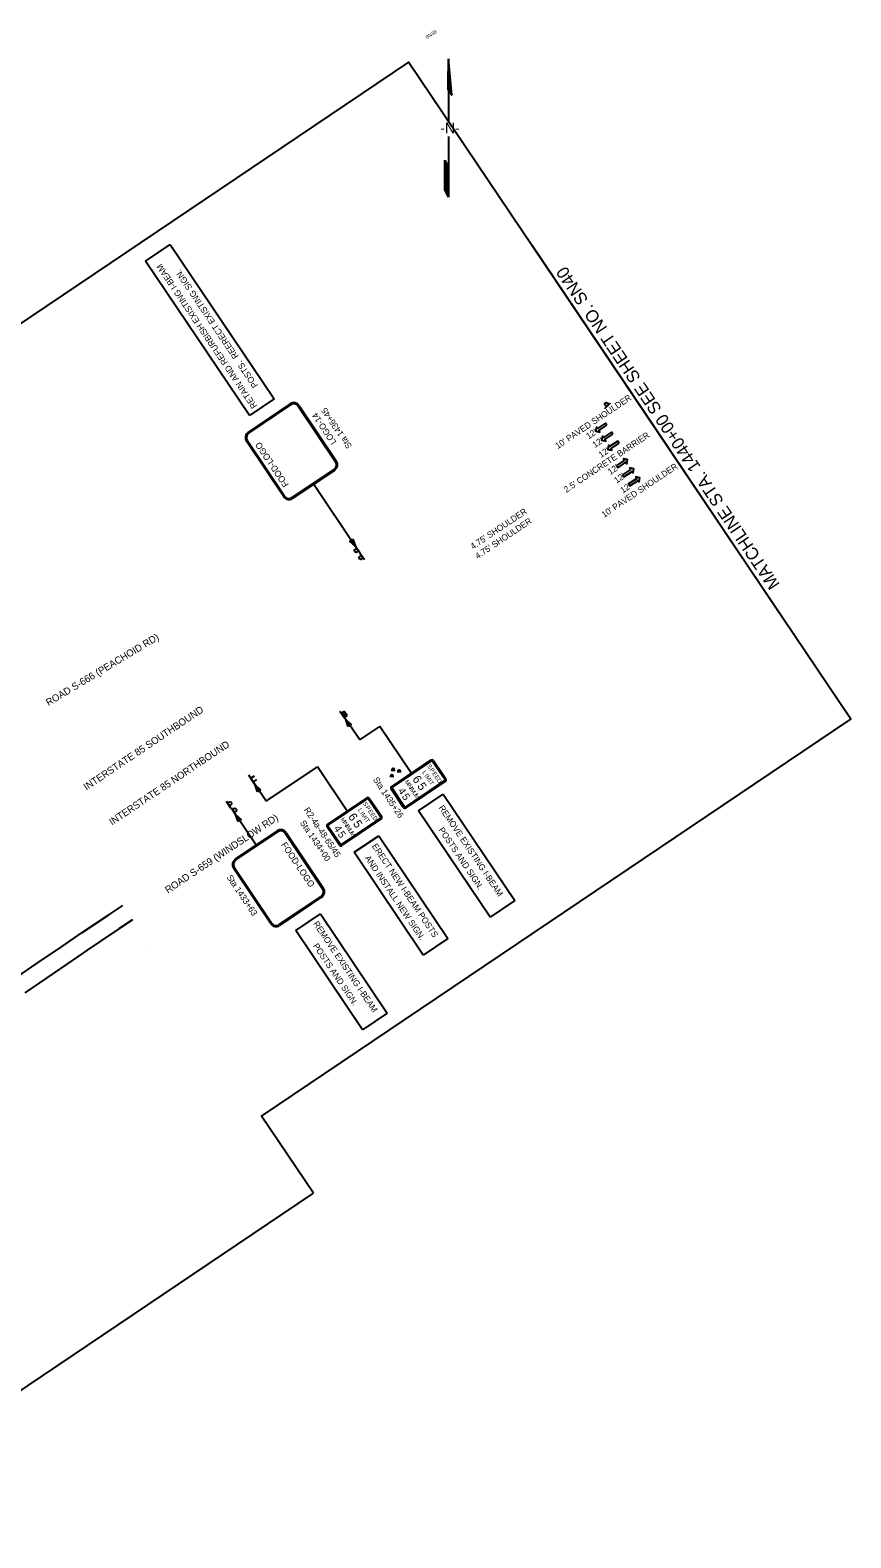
# Model space of a CAD drawing. Extents: x 1790709 to 1792453, y 1184078 to 1185781.
# Drawn here: x 1791525 to 1792453, y 1184078 to 1185781 of the extents above; entities that cross this region are included whole.
import ezdxf

# ---------------------------------------------------------------- set-up
doc = ezdxf.new("R2010")
doc.units = 0
for name, color, linetype in [('RD_EX_Road', 7, 'Continuous'), ('RD_PD_Final_LnLine', 7, 'Continuous'), ('RD_PD_Final_TX', 7, 'Continuous'), ('RD_SHT_MatchLine', 7, 'Continuous'), ('RD_SHT_ShtClip', 7, 'Continuous'), ('RD_SHT_TX', 7, 'Continuous'), ('RD_Sketch1', 7, 'Continuous'), ('RD_TX_RoadID', 7, 'Continuous'), ('SN_P_Signs', 7, 'Continuous')]:
    doc.layers.add(name, color=color, linetype=linetype)

# ---------------------------------------------------------------- blocks, each defined once
blk = doc.blocks.new('NA5')
at = {"layer": 'RD_Sketch1'}
for p, q in [((47.5, 65.9), (26.8, 37.4)), ((26.8, 30.6), (47.5, 65.9)), ((27.2, 37.5), (14.5, 19.8)), ((28.1, 38.3), (26.8, 30.6)), ((14.5, 19.8), (5.5, 7.2)), ((-3.5, -5.3), (-18.5, -26.3)), ((-18.5, -26.3), (-43.3, -60.9)), ((-30.6, -36.2), (-22.3, -24.7)), ((-22.3, -24.7), (-24, -34)), ((-41.6, -51.6), (-30.6, -36.2)), ((-43.3, -60.9), (-41.6, -51.6))]:
    blk.add_line(p, q, dxfattribs=at)
for points in [[(27.1, 37.6), (39.2, 54.5)], [(27.4, 37.8), (47.4, 65.8)], [(27.6, 37.9), (46.9, 64.9)], [(27.6, 35.5), (39, 51.5)], [(27.7, 36.2), (40.6, 54.2)], [(27.7, 36), (40.1, 53.3)], [(27.7, 35.8), (39.6, 52.4)], [(27.8, 38.1), (46.4, 64)], [(27.8, 36.8), (42.2, 56.8)], [(27.8, 36.6), (41.7, 56)], [(27.8, 36.4), (41.1, 55.1)], [(27.9, 37.4), (43.8, 59.5)], [(27.9, 37.2), (43.2, 58.6)], [(27.9, 37), (42.7, 57.7)], [(28, 38.1), (45.3, 62.2)], [(28, 37.9), (44.8, 61.3)], [(28, 37.7), (44.3, 60.4)], [(28.1, 38.3), (45.8, 63.1)], [(26.9, 37.5), (29.9, 41.7)], [(27, 32), (30.1, 36.3)], [(27, 31.8), (29.6, 35.4)], [(27, 31.5), (29.1, 34.5)], [(27.1, 32.6), (31.7, 39)], [(27.1, 32.4), (31.2, 38.1)], [(27.1, 32.2), (30.6, 37.2)], [(27.2, 33.2), (33.3, 41.6)], [(27.2, 33), (32.7, 40.7)], [(27.2, 32.8), (32.2, 39.9)], [(27.3, 33.9), (34.8, 44.3)], [(27.3, 33.7), (34.3, 43.4)], [(27.3, 33.4), (33.8, 42.5)], [(27.4, 34.5), (36.4, 47)], [(27.4, 34.3), (35.9, 46.1)], [(27.4, 34.1), (35.4, 45.2)], [(27.5, 34.9), (37.5, 48.8)], [(27.5, 34.7), (36.9, 47.9)], [(27.6, 35.3), (38.5, 50.6)], [(27.6, 35.1), (38, 49.7)], [(26.8, 30.7), (27, 30.9)], [(26.9, 31.3), (28.5, 33.6)], [(26.9, 31.1), (28, 32.7)], [(26.9, 30.9), (27.5, 31.8)], [(-43.3, -60.8), (-24, -33.9)], [(-43.2, -60.1), (-23.9, -33.2)], [(-43.2, -60.3), (-23.9, -33.4)], [(-43.2, -60.5), (-24, -33.6)], [(-43.1, -59.7), (-23.8, -32.8)], [(-43.1, -59.9), (-23.9, -33)], [(-43, -59), (-23.7, -32.1)], [(-43, -59.2), (-23.7, -32.3)], [(-43, -59.4), (-23.8, -32.5)], [(-42.9, -58.6), (-23.6, -31.7)], [(-42.9, -58.8), (-23.7, -31.9)], [(-42.8, -58.1), (-23.5, -31.2)], [(-42.8, -58.3), (-23.6, -31.4)], [(-42.7, -57.5), (-23.4, -30.6)], [(-42.7, -57.7), (-23.5, -30.8)], [(-42.7, -57.9), (-23.5, -31)], [(-42.6, -57), (-23.3, -30.1)], [(-42.6, -57.2), (-23.4, -30.4)], [(-42.5, -56.4), (-23.2, -29.5)], [(-42.5, -56.6), (-23.2, -29.7)], [(-42.5, -56.8), (-23.3, -29.9)], [(-42.4, -55.9), (-23.1, -29)], [(-42.4, -56.1), (-23.2, -29.3)], [(-42.3, -55.3), (-23, -28.4)], [(-42.3, -55.5), (-23, -28.6)], [(-42.3, -55.7), (-23.1, -28.8)], [(-42.2, -54.8), (-22.9, -27.9)], [(-42.2, -55), (-23, -28.2)], [(-42.1, -54.4), (-22.8, -27.5)], [(-42.1, -54.6), (-22.9, -27.7)], [(-42, -53.7), (-22.7, -26.8)], [(-42, -53.9), (-22.7, -27.1)], [(-42, -54.2), (-22.8, -27.3)], [(-41.9, -53.3), (-22.6, -26.4)], [(-41.9, -53.5), (-22.7, -26.6)], [(-41.8, -52.6), (-22.5, -25.7)], [(-41.8, -52.8), (-22.5, -26)], [(-41.8, -53.1), (-22.6, -26.2)], [(-41.7, -52.2), (-22.4, -25.3)], [(-41.7, -52.4), (-22.5, -25.5)], [(-41.6, -51.7), (-22.3, -24.9)], [(-41.6, -52), (-22.4, -25.1)]]:
    blk.add_lwpolyline(points, dxfattribs=at)
blk.add_text('-N-', height=11.81, rotation=324.3865, dxfattribs=at).set_placement((-8.8, 3))
blk = doc.blocks.new('SARRW2')
at = {"layer": 'RD_PD_Final_LnLine'}
blk.add_lwpolyline([(-12, 1.2), (-12, -1.2), (-2.8, -1.2), (-2.8, -2.8), (0, 0), (-2.8, 2.8), (-2.8, 1.2)], close=True, dxfattribs=at)

msp = doc.modelspace()

# ---------------------------------------------------------------- linework, layer by layer
at = {"layer": 'RD_EX_Road'}
for points in [[(1791510, 1184711.3), (1791533.3, 1184727.1), (1791561.9, 1184746.4), (1791584.1, 1184761.6), (1791614, 1184781.7), (1791629.9, 1184792.4)], [(1791640.9, 1184776.1), (1791625.5, 1184765.8), (1791604.7, 1184751.9), (1791589.6, 1184741.6), (1791573.9, 1184731), (1791544, 1184710.6), (1791519.1, 1184693.7)]]:
    msp.add_lwpolyline(points, dxfattribs=at)
at = {"layer": 'RD_SHT_MatchLine'}
msp.add_lwpolyline([(1792371.8, 1185122.9), (1792232.2, 1185330.3), (1792092.6, 1185537.7)], dxfattribs=at)
at = {"layer": 'RD_SHT_ShtClip'}
msp.add_lwpolyline([(1791845.3, 1184467.1), (1791786.7, 1184554.2), (1792452.8, 1185002.6), (1791953, 1185745.1), (1791953, 1185745.1), (1790708.7, 1184907.4), (1791267.1, 1184077.9)], close=True, dxfattribs=at)
at = {"layer": 'SN_P_Signs'}
for p, q in [((1791655.7, 1185520.1), (1791683.6, 1185538.9)), ((1791683.6, 1185538.9), (1791800.9, 1185364.7)), ((1791773, 1185345.9), (1791655.7, 1185520.1)), ((1791800.9, 1185364.7), (1791773, 1185345.9)), ((1792174.9, 1185353.8), (1792181.3, 1185360.1)), ((1791845.7, 1185268.1), (1791892.9, 1185197.9)), ((1791897.9, 1185190.5), (1791892.9, 1185197.9)), ((1791903, 1185182.6), (1791898, 1185190.1)), ((1791875.4, 1185011.8), (1791880.4, 1185004.3)), ((1791876.9, 1185010), (1791882, 1185002.5)), ((1791897.7, 1184979.2), (1791882, 1185002.5)), ((1791897.7, 1184979.2), (1791920.4, 1184994.5)), ((1791956.1, 1184941.5), (1791920.4, 1184994.5)), ((1791791.9, 1184910), (1791849.9, 1184949)), ((1791883.6, 1184898.9), (1791849.9, 1184949)), ((1791933.4, 1184945.2), (1791937.9, 1184945.2)), ((1791933.7, 1184926.4), (1791978.5, 1184956.6)), ((1791981, 1184956.1), (1791995.1, 1184935.2)), ((1791779.4, 1184928.4), (1791772.2, 1184939.3)), ((1791774.5, 1184935.9), (1791778.6, 1184938.6)), ((1791777.3, 1184931.7), (1791781.4, 1184934.5)), ((1791791.9, 1184910), (1791779.4, 1184928.4)), ((1791931.8, 1184938.3), (1791936.3, 1184938.3)), ((1791940.1, 1184943.5), (1791944.6, 1184943.5)), ((1791994.6, 1184932.7), (1791949.8, 1184902.5)), ((1791861.2, 1184883.9), (1791906, 1184914)), ((1791908.5, 1184913.5), (1791922.6, 1184892.6)), ((1791947.3, 1184903), (1791933.2, 1184923.9)), ((1791964.2, 1184899.3), (1791992.1, 1184918.1)), ((1791992.1, 1184918.1), (1792073.1, 1184797.8)), ((1791746.7, 1184910), (1791751.7, 1184902.6)), ((1791752.3, 1184902.6), (1791757.4, 1184895.2)), ((1791780.7, 1184860.5), (1791757.4, 1184895.2)), ((1792045.2, 1184779), (1791964.2, 1184899.3)), ((1791874.8, 1184860.5), (1791860.7, 1184881.4)), ((1791922.1, 1184890.1), (1791877.3, 1184860)), ((1791891.4, 1184852.3), (1791919.2, 1184871.1)), ((1791919.2, 1184871.1), (1791997.4, 1184754.9)), ((1791969.5, 1184736.2), (1791891.4, 1184852.3)), ((1792073.1, 1184797.8), (1792045.2, 1184779)), ((1791825.5, 1184763.9), (1791853.4, 1184782.7)), ((1791853.4, 1184782.7), (1791928.8, 1184670.7)), ((1791900.9, 1184651.9), (1791825.5, 1184763.9)), ((1791660.4, 1184747.2), (1791660.4, 1184747.2)), ((1791997.4, 1184754.9), (1791969.5, 1184736.2)), ((1791928.8, 1184670.7), (1791900.9, 1184651.9))]:
    msp.add_line(p, q, dxfattribs=at)
for points in [[(1791771.5, 1185326.7), (1791819.3, 1185358.9)], [(1791772.2, 1185325.7), (1791820, 1185357.9)], [(1791828.3, 1185356.2), (1791870.5, 1185293.5)], [(1791829.3, 1185356.9), (1791871.5, 1185294.2)], [(1791811.8, 1185254), (1791769.6, 1185316.7)], [(1791812.8, 1185254.7), (1791770.6, 1185317.4)], [(1791868.9, 1185285.2), (1791821.1, 1185253)], [(1791869.5, 1185284.2), (1791821.8, 1185252)], [(1791934, 1184926), (1791978.8, 1184956.2)], [(1791934.4, 1184925.4), (1791979.2, 1184955.6)], [(1791980, 1184955.4), (1791994.1, 1184934.5)], [(1791980.7, 1184955.8), (1791994.7, 1184934.9)], [(1791993.9, 1184933.7), (1791949.1, 1184903.5)], [(1791994.4, 1184933), (1791949.6, 1184902.9)], [(1791861.4, 1184883.5), (1791906.2, 1184913.6)], [(1791861.9, 1184882.9), (1791906.7, 1184913)], [(1791907.5, 1184912.9), (1791921.6, 1184892)], [(1791908.1, 1184913.3), (1791922.2, 1184892.4)], [(1791947.7, 1184903.2), (1791933.6, 1184924.2)], [(1791948.3, 1184903.7), (1791934.2, 1184924.6)], [(1791756.8, 1184844.4), (1791804.6, 1184876.5)], [(1791875.2, 1184860.7), (1791861.1, 1184881.6)], [(1791875.8, 1184861.1), (1791861.7, 1184882)], [(1791921.4, 1184891.1), (1791876.6, 1184861)], [(1791921.8, 1184890.5), (1791877, 1184860.3)], [(1791757.5, 1184843.4), (1791805.3, 1184875.5)], [(1791813.6, 1184873.9), (1791855.8, 1184811.2)], [(1791814.6, 1184874.6), (1791856.8, 1184811.9)], [(1791797.1, 1184771.7), (1791754.9, 1184834.4)], [(1791798.1, 1184772.3), (1791755.9, 1184835)], [(1791854.2, 1184802.9), (1791806.4, 1184770.7)], [(1791854.9, 1184801.9), (1791807.1, 1184769.7)]]:
    msp.add_lwpolyline(points, dxfattribs=at)
for points in [[(1791890, 1185205.9), (1791892.9, 1185197.9), (1791886.6, 1185203.6)], [(1791884.8, 1184994.5), (1791882, 1185002.5), (1791888.2, 1184996.8)], [(1791782.3, 1184920.5), (1791779.4, 1184928.4), (1791785.7, 1184922.8)], [(1791760.2, 1184887.2), (1791757.4, 1184895.2), (1791763.6, 1184889.5)]]:
    msp.add_lwpolyline(points, close=True, dxfattribs=at)
for centre, radius in [((1792176.7, 1185358.4), 2), ((1791893.7, 1185193.1), 2), ((1791898.8, 1185185.2), 2), ((1791879.6, 1185009.2), 2), ((1791881.1, 1185007.3), 2), ((1791935.6, 1184946.2), 1), ((1791942.3, 1184944.5), 1), ((1791934.1, 1184939.3), 1), ((1791750.9, 1184907.4), 2), ((1791756.5, 1184900), 2)]:
    msp.add_circle(centre, radius, dxfattribs=at)
for centre, radius, start, end in [((1791823.3, 1185352.9), 7.2, 33.9476, 123.9476), ((1791823.3, 1185352.9), 6, 33.9476, 123.9476), ((1791775.5, 1185320.7), 7.2, 123.9476, 213.9476), ((1791775.5, 1185320.7), 6, 123.9476, 213.9476), ((1791865.5, 1185290.2), 6, 303.9476, 33.9476), ((1791865.5, 1185290.2), 7.2, 303.9476, 33.9476), ((1791817.7, 1185258), 7.2, 213.9476, 303.9476), ((1791817.7, 1185258), 6, 213.9476, 303.9476), ((1791979.5, 1184955.1), 1.8, 33.9476, 123.9476), ((1791979.5, 1184955.1), 1.35, 33.9476, 123.9476), ((1791979.5, 1184955.1), 0.6, 33.9476, 123.9476), ((1791993.6, 1184934.2), 0.6, 303.9476, 33.9476), ((1791993.6, 1184934.2), 1.35, 303.9476, 33.9476), ((1791993.6, 1184934.2), 1.8, 303.9476, 33.9476), ((1791907, 1184912.5), 1.8, 33.9476, 123.9476), ((1791907, 1184912.5), 1.35, 33.9476, 123.9476), ((1791907, 1184912.5), 0.6, 33.9476, 123.9476), ((1791934.7, 1184924.9), 1.8, 123.9476, 213.9476), ((1791934.7, 1184924.9), 1.35, 123.9476, 213.9476), ((1791934.7, 1184924.9), 0.6, 123.9476, 213.9476), ((1791948.8, 1184904), 1.8, 213.9476, 303.9476), ((1791948.8, 1184904), 1.35, 213.9476, 303.9476), ((1791948.8, 1184904), 0.6, 213.9476, 303.9476), ((1791808.6, 1184870.6), 7.2, 33.9476, 123.9476), ((1791808.6, 1184870.6), 6, 33.9476, 123.9476), ((1791862.2, 1184882.4), 1.8, 123.9476, 213.9476), ((1791862.2, 1184882.4), 1.35, 123.9476, 213.9476), ((1791862.2, 1184882.4), 0.6, 123.9476, 213.9476), ((1791921.1, 1184891.6), 0.6, 303.9476, 33.9476), ((1791921.1, 1184891.6), 1.35, 303.9476, 33.9476), ((1791921.1, 1184891.6), 1.8, 303.9476, 33.9476), ((1791876.3, 1184861.5), 1.8, 213.9476, 303.9476), ((1791876.3, 1184861.5), 1.35, 213.9476, 303.9476), ((1791876.3, 1184861.5), 0.6, 213.9476, 303.9476), ((1791760.9, 1184838.4), 7.2, 123.9476, 213.9476), ((1791760.9, 1184838.4), 6, 123.9476, 213.9476), ((1791850.9, 1184807.8), 6, 303.9476, 33.9476), ((1791850.9, 1184807.8), 7.2, 303.9476, 33.9476), ((1791803.1, 1184775.7), 7.2, 213.9476, 303.9476), ((1791803.1, 1184775.7), 6, 213.9476, 303.9476)]:
    msp.add_arc(centre, radius, start, end, dxfattribs=at)

# ---------------------------------------------------------------- block references
at = {"layer": 'RD_PD_Final_LnLine', "xscale": 1.1999999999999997}
for p, yscale, rotation in [((1792164.3, 1185328), 1.2000000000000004, -146.05256015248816), ((1792171.1, 1185317.8), 1.2000000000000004, -146.05256015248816), ((1792178.1, 1185307.5), 1.2000000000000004, -146.05256015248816), ((1792200.5, 1185296), 1.2, 33.94743984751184), ((1792207.5, 1185285.6), 1.2, 33.94743984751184), ((1792214.3, 1185275.4), 1.2, 33.94743984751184)]:
    msp.add_blockref('SARRW2', p, dxfattribs=dict(at, yscale=yscale, rotation=rotation))
at = {"layer": 'RD_SHT_MatchLine', "rotation": 35.61349782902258}
msp.add_blockref('NA5', (1791997.7, 1185667.3), dxfattribs=at)

# ---------------------------------------------------------------- texts
at = {"layer": 'RD_PD_Final_TX'}
for s, p in [("10' PAVED SHOULDER", (1792121.6, 1185307.7)), ("2.5' CONCRETE BARRIER", (1792131.3, 1185258.2)), ("12'", (1792156.4, 1185318.7)), ("12'", (1792163.6, 1185309)), ("12'", (1792170.5, 1185297.7)), ("10' PAVED SHOULDER", (1792173.9, 1185230.1)), ("12'", (1792181, 1185278.4)), ("12'", (1792188.1, 1185268.8)), ("12'", (1792195.1, 1185257.5)), ("4.75' SHOULDER", (1792025.6, 1185194.1)), ("4.75' SHOULDER", (1792031, 1185183.3))]:
    msp.add_text(s, height=7, rotation=33.9474, dxfattribs=at).set_placement(p)
at = {"layer": 'RD_SHT_MatchLine'}
msp.add_text('MATCHLINE STA. 1440+00 SEE SHEET NO. SN40', height=14, rotation=123.9476, dxfattribs=at).set_placement((1792373, 1185155.1))
at = {"layer": 'RD_SHT_TX'}
msp.add_text('SN39', height=4, rotation=33.9476, dxfattribs=at).set_placement((1791973.8, 1185770.7))
at = {"layer": 'RD_TX_RoadID'}
for s, rotation, p in [('ROAD S-666 (PEACHOID RD)', 31.1015, (1791546, 1185017.3)), ('INTERSTATE 85 SOUTHBOUND', 33.9476, (1791588.9, 1184921.9)), ('INTERSTATE 85 NORTHBOUND', 33.9476, (1791617.8, 1184882.4)), ('ROAD S-659 (WINDSLOW RD)', 33.8066, (1791681, 1184805.5))]:
    msp.add_text(s, height=8, rotation=rotation, dxfattribs=at).set_placement(p)
at = {"layer": 'SN_P_Signs'}
for s, height, rotation, p in [('RETAIN AND REFURBISH EXISTING I-BEAM', 7, 123.9477, (1791782, 1185356.5)), ('POSTS.  REERECT EXISTING SIGN.', 7, 123.9477, (1791783.1, 1185379.9)), ('Sta 1436+45', 7, 123.9477, (1791889.3, 1185311.2)), ('LOGO-14', 7, 123.9477, (1791871.8, 1185315.9)), ('FOOD-LOGO', 7.2, 123.9476, (1791817.9, 1185267.8)), ('L', 4.8, 303.9476, (1791968, 1184942.7)), ('S', 4.8, 303.9476, (1791973.7, 1184949.8)), ('P', 4.8, 303.9476, (1791976.5, 1184945.6)), ('Sta 1435+26', 7, 303.9477, (1791912.4, 1184934.4)), ('M', 4.8, 303.9476, (1791948.3, 1184932.1)), ('I', 4.8, 303.9476, (1791950.6, 1184928.7)), ('N', 4.8, 303.9476, (1791951.6, 1184927.3)), ('6', 9.6, 303.9476, (1791956.8, 1184935.1)), ('5', 9.6, 303.9476, (1791962.2, 1184927.2)), ('I', 4.8, 303.9476, (1791970.5, 1184938.9)), ('M', 4.8, 303.9476, (1791971.7, 1184937.2)), ('I', 4.8, 303.9476, (1791974.8, 1184932.5)), ('T', 4.8, 303.9476, (1791975.8, 1184931)), ('E', 4.8, 303.9476, (1791979.3, 1184941.4)), ('E', 4.8, 303.9476, (1791981.9, 1184937.6)), ('D', 4.8, 303.9476, (1791984.4, 1184933.8)), ('4', 8.4, 303.9476, (1791940.5, 1184921.7)), ('5', 8.4, 303.9476, (1791944.9, 1184915.3)), ('I', 4.8, 303.9476, (1791953.6, 1184924.3)), ('M', 4.8, 303.9476, (1791954.5, 1184922.9)), ('U', 4.8, 303.9476, (1791956.8, 1184919.5)), ('M', 4.8, 303.9476, (1791958.9, 1184916.5)), ('R2-4a-48-65/45', 7, 303.9477, (1791834.3, 1184900.2)), ('6', 9.6, 303.9476, (1791884.2, 1184892.6)), ('L', 4.8, 303.9476, (1791895.4, 1184900.2)), ('I', 4.8, 303.9476, (1791898, 1184896.4)), ('M', 4.8, 303.9476, (1791899.1, 1184894.7)), ('S', 4.8, 303.9476, (1791901.1, 1184907.3)), ('P', 4.8, 303.9476, (1791904, 1184903.1)), ('E', 4.8, 303.9476, (1791906.8, 1184898.8)), ('E', 4.8, 303.9476, (1791909.3, 1184895.1)), ('D', 4.8, 303.9476, (1791911.9, 1184891.3)), ('REMOVE EXISTING I-BEAM', 7, 303.9477, (1791986.5, 1184902.6)), ('Sta 1434+00', 7, 303.9477, (1791829.8, 1184885.6)), ('4', 8.4, 303.9476, (1791868, 1184879.2)), ('5', 8.4, 303.9476, (1791872.3, 1184872.7)), ('M', 4.8, 303.9476, (1791875.8, 1184889.6)), ('I', 4.8, 303.9476, (1791878.1, 1184886.2)), ('N', 4.8, 303.9476, (1791879, 1184884.8)), ('I', 4.8, 303.9476, (1791881.1, 1184881.8)), ('M', 4.8, 303.9476, (1791882, 1184880.4)), ('U', 4.8, 303.9476, (1791884.3, 1184876.9)), ('M', 4.8, 303.9476, (1791886.3, 1184873.9)), ('5', 9.6, 303.9476, (1791889.6, 1184884.6)), ('I', 4.8, 303.9476, (1791902.3, 1184890)), ('T', 4.8, 303.9476, (1791903.3, 1184888.5)), ('POSTS AND SIGN. ', 7, 303.9477, (1791986.4, 1184877.6)), ('FOOD-LOGO', 7.2, 303.9476, (1791808.5, 1184860.8)), ('ERECT NEW I-BEAM POSTS', 7, 303.9477, (1791911.1, 1184859.3)), ('AND INSTALL NEW SIGN.', 7, 303.9477, (1791903.2, 1184845.9)), ('Sta 1433+63', 7, 303.9477, (1791747, 1184824)), ('REMOVE EXISTING I-BEAM', 7, 303.9477, (1791844.7, 1184771.6)), ('POSTS AND SIGN.', 7, 303.9477, (1791844.6, 1184746.6))]:
    msp.add_text(s, height=height, rotation=rotation, dxfattribs=at).set_placement(p)

doc.saveas('drawing.dxf')
